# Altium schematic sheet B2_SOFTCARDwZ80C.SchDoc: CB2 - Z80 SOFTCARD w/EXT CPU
size A1; CheckedBy: SRKH; Engineer: SRKH; DocumentNumber: 1; Revision: 1.00; SheetNumber: 1; SheetTotal: 21; PageSetup: Record=PageOptions|CenterHorizontal=True|CenterVertical=True|PrintScale=0.50|XCorrection=1.00|YCorrection=1.00|PrintKind=2|BorderSize=5000000|LeftOffset=0|BottomOffset=0|Orientation=2|PaperLength=1000|PaperWidth=1000|Scale=100|PaperSource=7|PrintQuality=-4|MediaType=1|DitherType=10|PaperKind=A3 (297 x 420mm)|PrintScaleMode=1
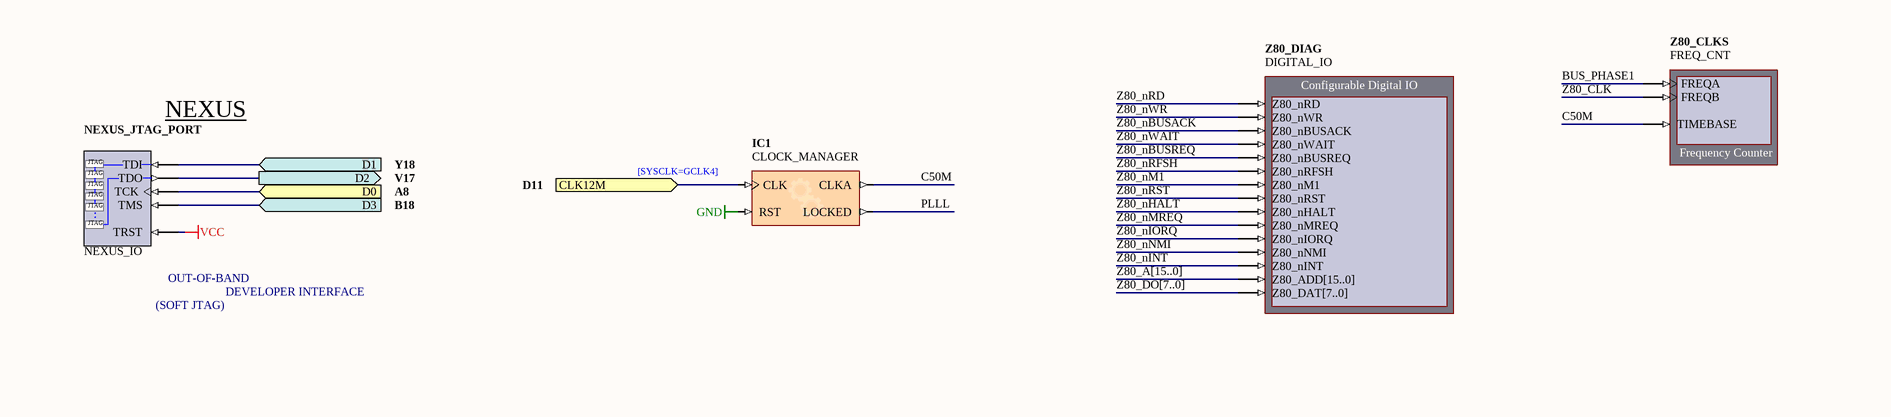
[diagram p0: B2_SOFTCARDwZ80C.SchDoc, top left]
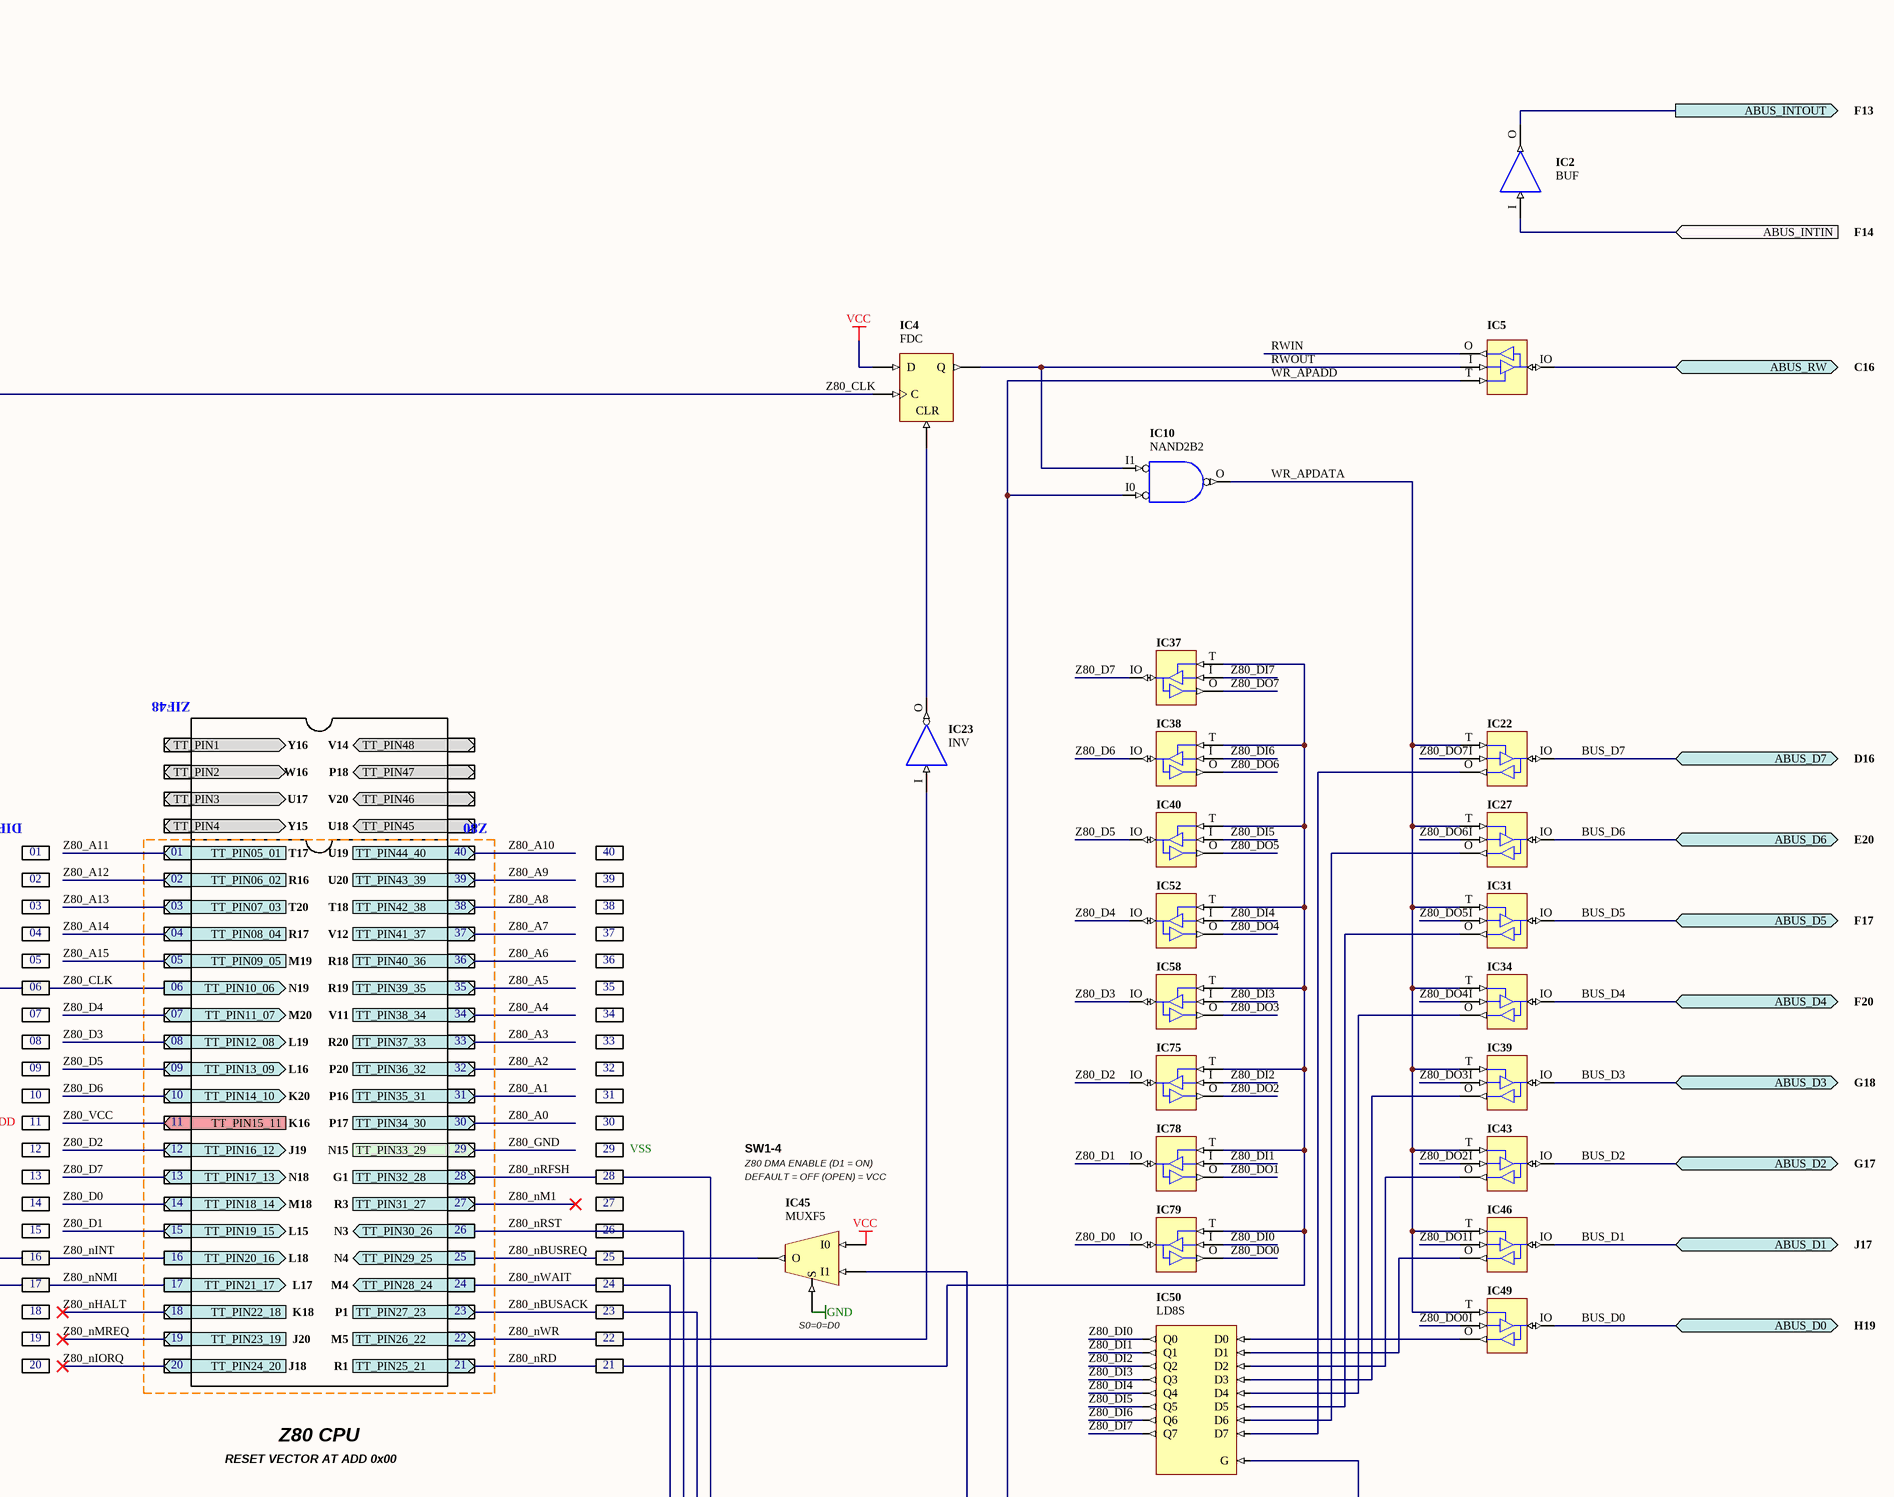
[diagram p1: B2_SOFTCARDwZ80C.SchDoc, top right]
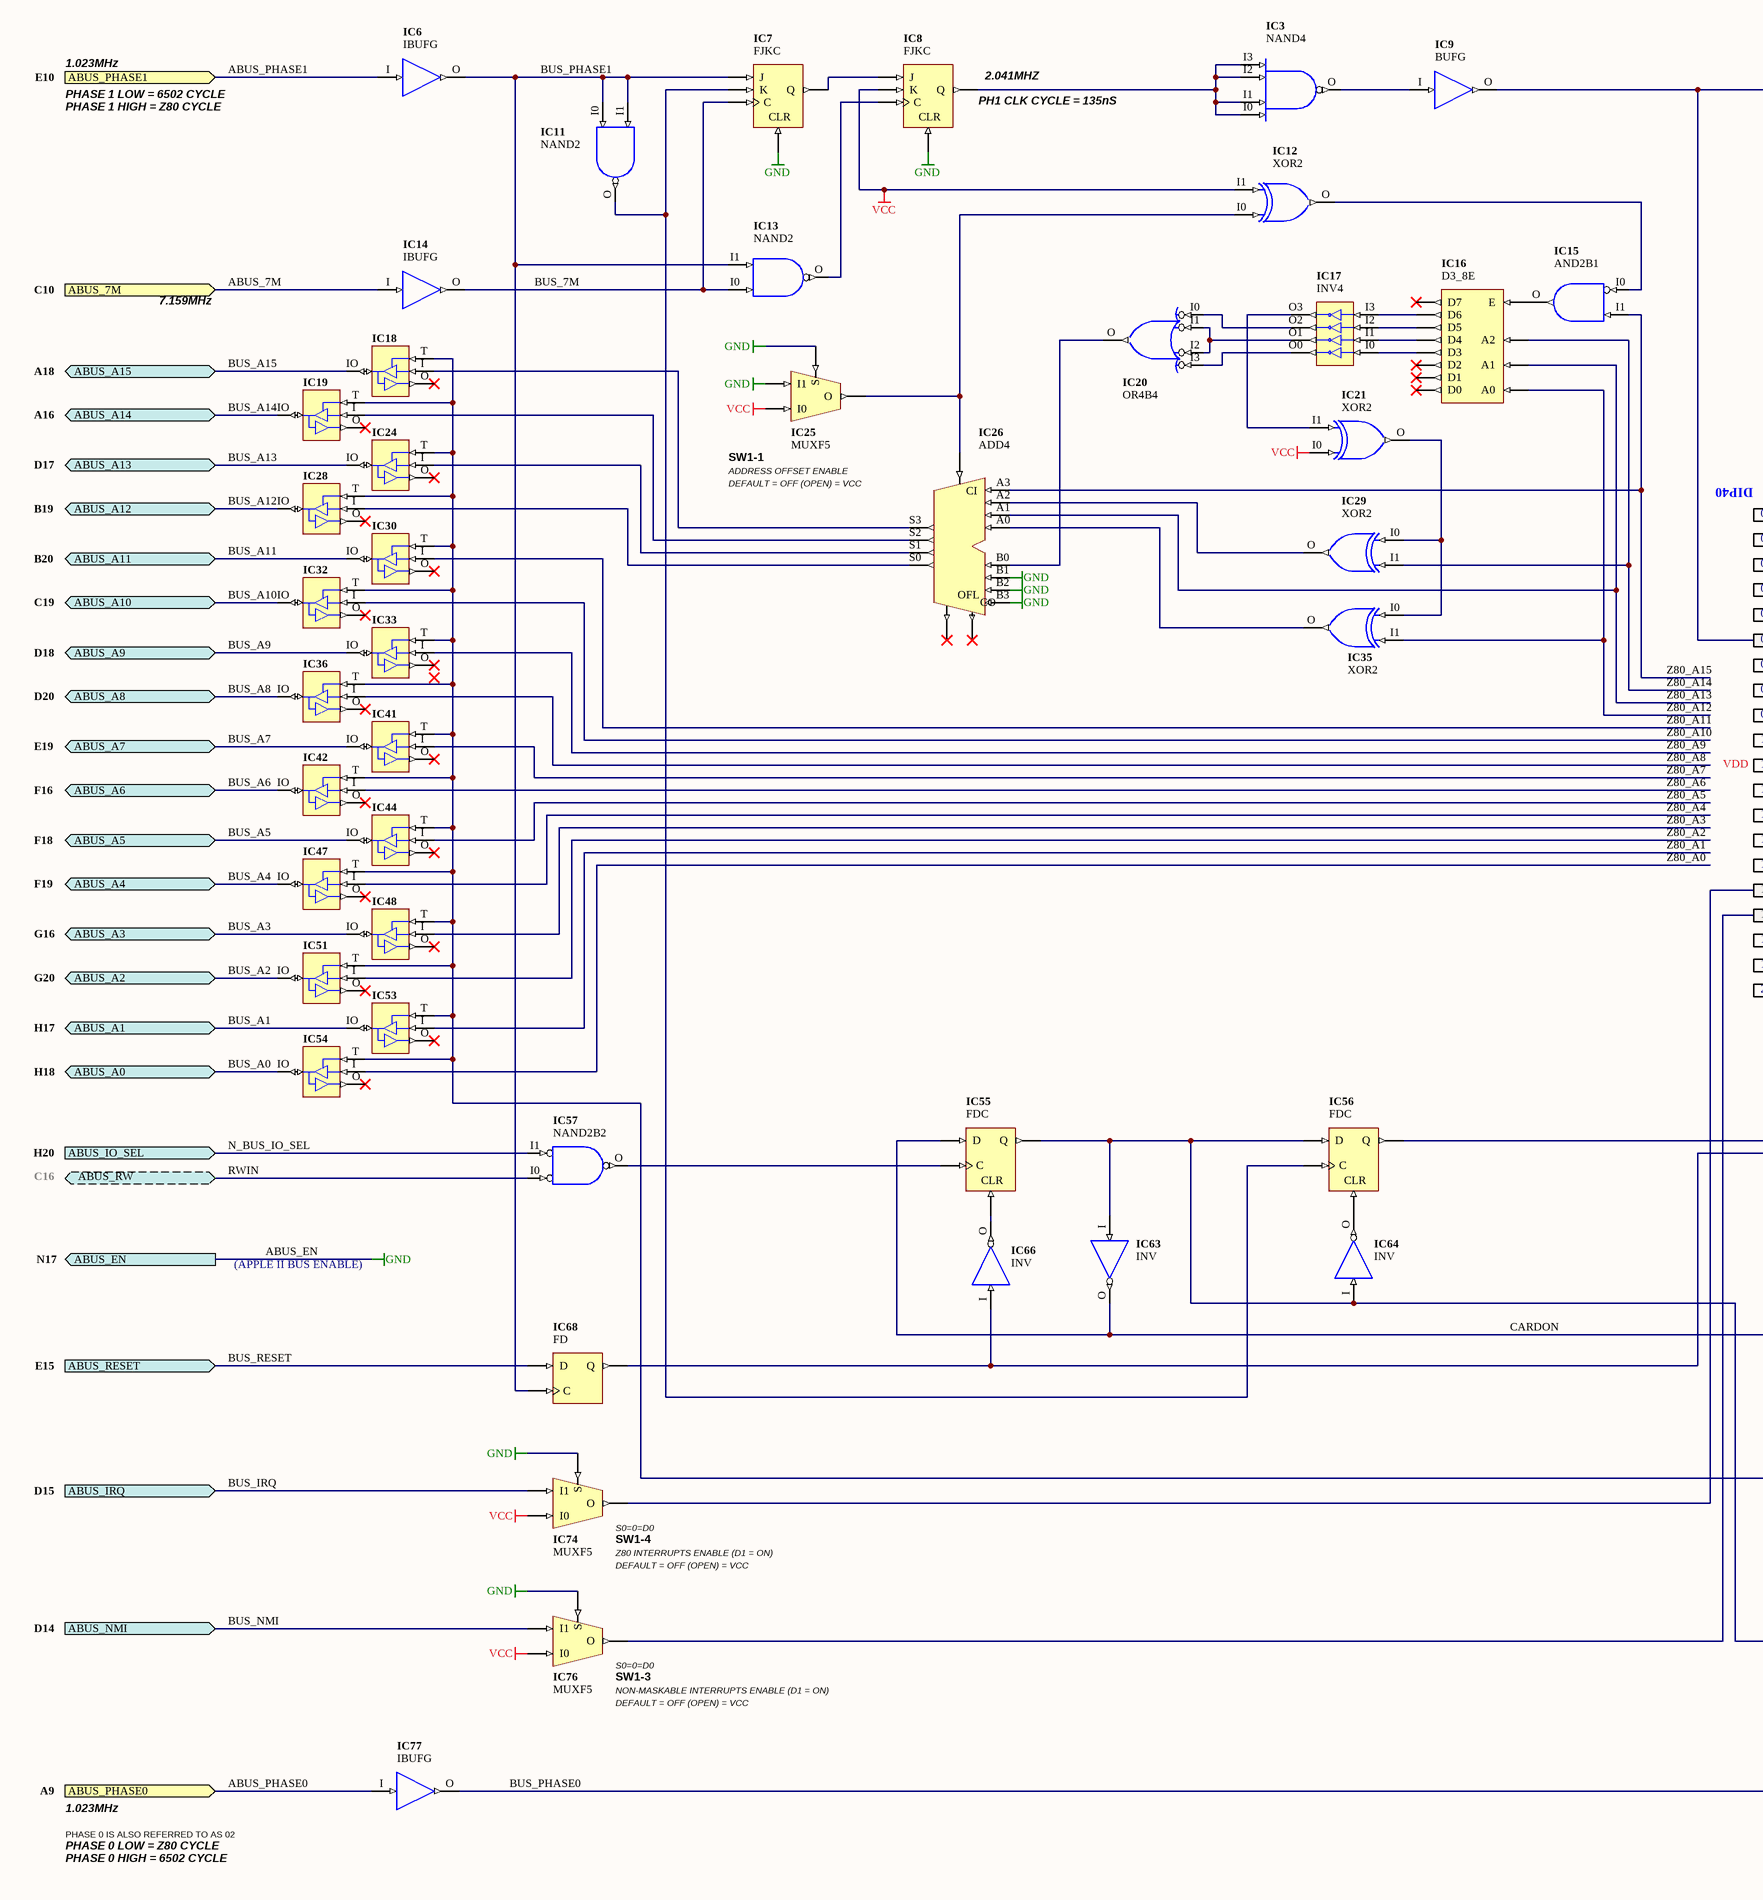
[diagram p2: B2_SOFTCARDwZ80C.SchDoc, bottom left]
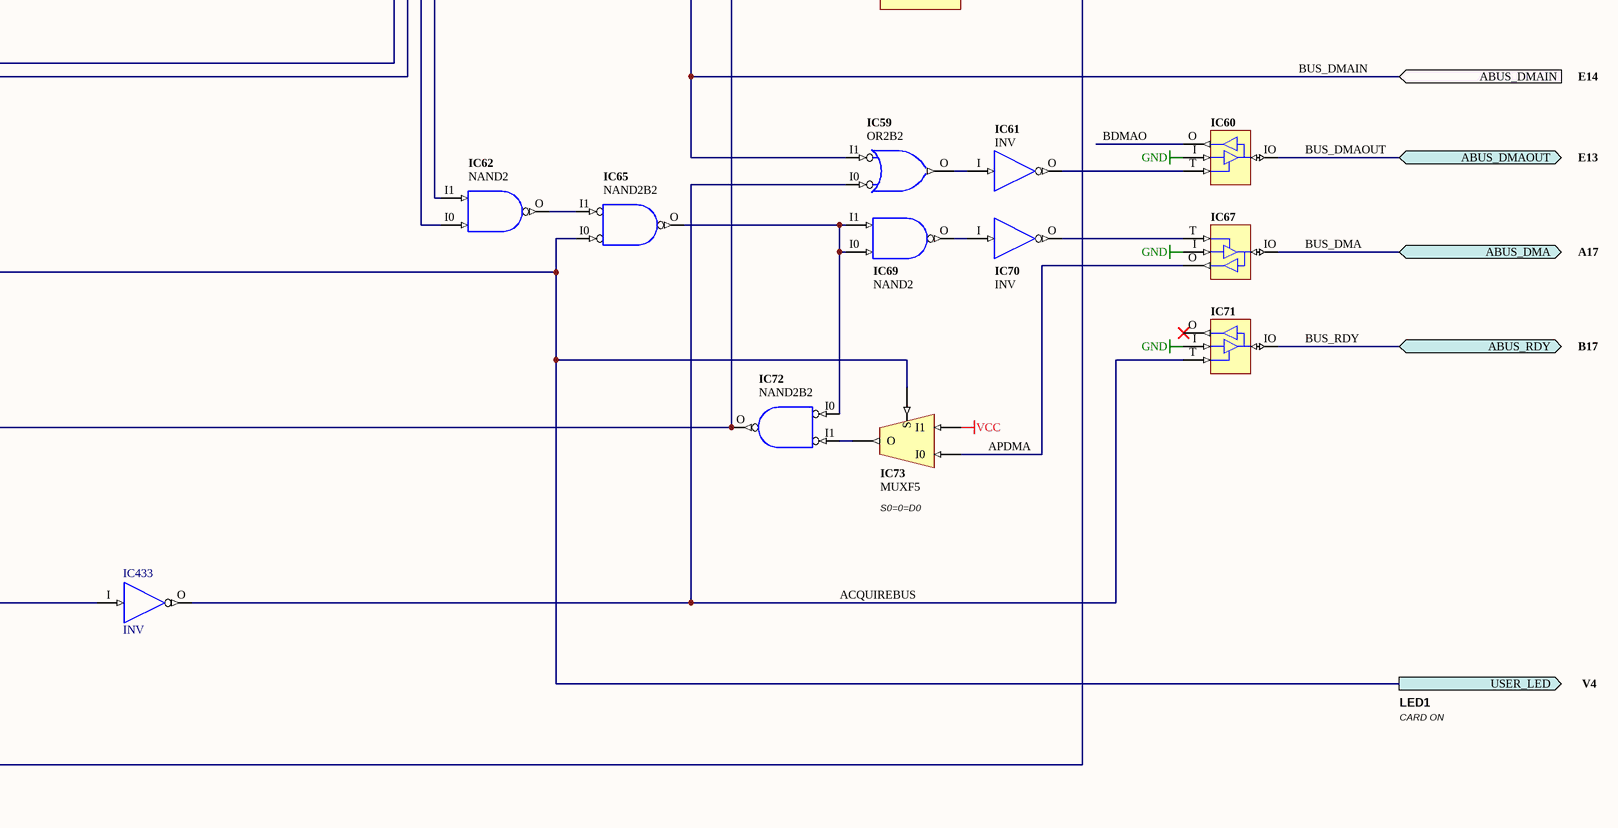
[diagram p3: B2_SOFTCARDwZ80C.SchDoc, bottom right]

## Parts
IC1  CLOCK_MANAGER
IC2  BUF
IC3  NAND4
IC4  FDC
IC5  IOBUF  (value not drawn)
IC6  IBUFG
IC7  FJKC
IC8  FJKC
IC9  BUFG
IC10  NAND2B2
IC11  NAND2
IC12  XOR2
IC13  NAND2
IC14  IBUFG
IC15  AND2B1
IC16  D3_8E
IC17  INV4
IC18  IOBUF  (value not drawn)
IC19  IOBUF  (value not drawn)
IC20  OR4B4
IC21  XOR2
IC22  IOBUF  (value not drawn)
IC23  INV
IC24  IOBUF  (value not drawn)
IC25  MUXF5
IC26  ADD4
IC27  IOBUF  (value not drawn)
IC28  IOBUF  (value not drawn)
IC29  XOR2
IC30  IOBUF  (value not drawn)
IC31  IOBUF  (value not drawn)
IC32  IOBUF  (value not drawn)
IC33  IOBUF  (value not drawn)
IC34  IOBUF  (value not drawn)
IC35  XOR2
IC36  IOBUF  (value not drawn)
IC37  IOBUF  (value not drawn)
IC38  IOBUF  (value not drawn)
IC39  IOBUF  (value not drawn)
IC40  IOBUF  (value not drawn)
IC41  IOBUF  (value not drawn)
IC42  IOBUF  (value not drawn)
IC43  IOBUF  (value not drawn)
IC44  IOBUF  (value not drawn)
IC45  MUXF5
IC46  IOBUF  (value not drawn)
IC47  IOBUF  (value not drawn)
IC48  IOBUF  (value not drawn)
IC49  IOBUF  (value not drawn)
IC50  LD8S
IC51  IOBUF  (value not drawn)
IC52  IOBUF  (value not drawn)
IC53  IOBUF  (value not drawn)
IC54  IOBUF  (value not drawn)
IC55  FDC
IC56  FDC
IC57  NAND2B2
IC58  IOBUF  (value not drawn)
IC59  OR2B2
IC60  IOBUF  (value not drawn)
IC61  INV
IC62  NAND2
IC63  INV
IC64  INV
IC65  NAND2B2
IC66  INV
IC67  IOBUF  (value not drawn)
IC68  FD
IC69  NAND2
IC70  INV
IC71  IOBUF  (value not drawn)
IC72  NAND2B2
IC73  MUXF5
IC74  MUXF5
IC75  IOBUF  (value not drawn)
IC76  MUXF5
IC77  IBUFG
IC78  IOBUF  (value not drawn)
IC79  IOBUF  (value not drawn)
IC433  INV
NEXUS_JTAG_PORT  NEXUS_IO
Z80_CLKS  FREQ_CNT
Z80_DIAG  DIGITAL_IO

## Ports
ABUS_7M (in, see C10), ABUS_A0 (bidir, see H18), ABUS_A1 (bidir, see H17), ABUS_A2 (bidir, see G20), ABUS_A3 (bidir, see G16), ABUS_A4 (bidir, see F19), ABUS_A5 (bidir, see F18), ABUS_A6 (bidir, see F16), ABUS_A7 (bidir, see E19), ABUS_A8 (bidir, see D20), ABUS_A9 (bidir, see D18), ABUS_A10 (bidir, see C19), ABUS_A11 (bidir, see B20), ABUS_A12 (bidir, see B19), ABUS_A13 (bidir, see D17), ABUS_A14 (bidir, see A16), ABUS_A15 (bidir, see A18), ABUS_D0 (bidir, see H19), ABUS_D1 (bidir, see J17), ABUS_D2 (bidir, see G17), ABUS_D3 (bidir, see G18), ABUS_D4 (bidir, see F20), ABUS_D5 (bidir, see F17), ABUS_D6 (bidir, see E20), ABUS_D7 (bidir, see D16), ABUS_DMA (bidir, see A17), ABUS_DMAIN (in, see E14), ABUS_DMAOUT (bidir, see E13), ABUS_EN (out, see N17), ABUS_INTIN (in, see F14), ABUS_INTOUT (out, see F13), ABUS_IO_SEL (in, see H20), ABUS_IRQ (in, see D15), ABUS_NMI (in, see D14), ABUS_PHASE0 (in, see A9), ABUS_PHASE1 (in, see E10), ABUS_RDY (bidir, see B17), ABUS_RESET (in, see E15), ABUS_RW (bidir, see C16), CLK12M (in, see D11), D0 (in, see A8), D1 (in, see Y18), D2 (out, see V17), D3 (in, see B18), TT_PIN1 (bidir, see Y16), TT_PIN2 (bidir, see W16), TT_PIN3 (bidir, see U17), TT_PIN4 (bidir, see Y15), TT_PIN05_01 (in, see T17), TT_PIN06_02 (in, see R16), TT_PIN07_03 (in, see T20), TT_PIN08_04 (in, see R17), TT_PIN09_05 (in, see M19), TT_PIN10_06 (out, see N19), TT_PIN11_07 (bidir, see M20), TT_PIN12_08 (bidir, see L19), TT_PIN13_09 (bidir, see L16), TT_PIN14_10 (bidir, see K20), TT_PIN15_11 (in, see K16), TT_PIN16_12 (bidir, see J19), TT_PIN17_13 (bidir, see N18), TT_PIN18_14 (bidir, see M18), TT_PIN19_15 (bidir, see L15), TT_PIN20_16 (out, see L18), TT_PIN21_17 (out, see L17), TT_PIN22_18 (in, see K18), TT_PIN23_19 (in, see J20), TT_PIN24_20 (in, see J18), TT_PIN25_21 (in, see R1), TT_PIN26_22 (in, see M5), TT_PIN27_23 (in, see P1), TT_PIN28_24 (out, see M4), TT_PIN29_25 (out, see N4), TT_PIN30_26 (out, see N3), TT_PIN31_27 (in, see R3), TT_PIN32_28 (in, see G1), TT_PIN33_29 (in, see N15), TT_PIN34_30 (in, see P17), TT_PIN35_31 (in, see P16), TT_PIN36_32 (in, see P20), TT_PIN37_33 (in, see R20), TT_PIN38_34 (in, see V11), TT_PIN39_35 (in, see R19), TT_PIN40_36 (in, see R18), TT_PIN41_37 (in, see V12), TT_PIN42_38 (in, see T18), TT_PIN43_39 (in, see U20), TT_PIN44_40 (in, see U19), TT_PIN45 (bidir, see U18), TT_PIN46 (bidir, see V20), TT_PIN47 (bidir, see P18), TT_PIN48 (bidir, see V14), USER_LED (out, see V4)

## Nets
ABUS_EN: IC1.RST IC7.CLR IC8.CLR IC25.I1 IC25.S IC26.B1 IC26.B2 IC26.B3 IC45.S IC60.I IC67.I IC71.I IC74.S IC76.S ; port ABUS_EN  [also labelled GND]
VCC: IC4.D IC8.K IC12.I1 IC21.I0 IC25.I0 IC45.I0 IC73.I1 IC74.I0 IC76.I0 NEXUS_JTAG_PORT.TRST
ABUS_7M: IC14.I ; port ABUS_7M
ABUS_INTIN: IC2.I ; port ABUS_INTIN
ABUS_INTOUT: IC2.O ; port ABUS_INTOUT
ABUS_PHASE0: IC77.I ; port ABUS_PHASE0
ABUS_PHASE1: IC6.I ; port ABUS_PHASE1
ABUS_RW: IC5.IO ; port ABUS_RW
ACQUIREBUS: IC59.I0 IC71.T IC433.O
APDMA: IC67.O IC73.I0
BDMAO: IC60.O
BUS_7M: IC7.C IC13.I0 IC14.O
BUS_A0: IC54.IO ; port ABUS_A0
BUS_A1: IC53.IO ; port ABUS_A1
BUS_A2: IC51.IO ; port ABUS_A2
BUS_A3: IC48.IO ; port ABUS_A3
BUS_A4: IC47.IO ; port ABUS_A4
BUS_A5: IC44.IO ; port ABUS_A5
BUS_A6: IC42.IO ; port ABUS_A6
BUS_A7: IC41.IO ; port ABUS_A7
BUS_A8: IC36.IO ; port ABUS_A8
BUS_A9: IC33.IO ; port ABUS_A9
BUS_A10: IC32.IO ; port ABUS_A10
BUS_A11: IC30.IO ; port ABUS_A11
BUS_A12: IC28.IO ; port ABUS_A12
BUS_A13: IC24.IO ; port ABUS_A13
BUS_A14: IC19.IO ; port ABUS_A14
BUS_A15: IC18.IO ; port ABUS_A15
BUS_D0: IC49.IO ; port ABUS_D0
BUS_D1: IC46.IO ; port ABUS_D1
BUS_D2: IC43.IO ; port ABUS_D2
BUS_D3: IC39.IO ; port ABUS_D3
BUS_D4: IC34.IO ; port ABUS_D4
BUS_D5: IC31.IO ; port ABUS_D5
BUS_D6: IC27.IO ; port ABUS_D6
BUS_D7: IC22.IO ; port ABUS_D7
BUS_DMA: IC67.IO ; port ABUS_DMA
BUS_DMAIN: IC45.I1 IC59.I1 ; port ABUS_DMAIN
BUS_DMAOUT: IC60.IO ; port ABUS_DMAOUT
BUS_IRQ: IC74.I1 ; port ABUS_IRQ
BUS_NMI: IC76.I1 ; port ABUS_NMI
BUS_PHASE0: IC50.G IC77.O
BUS_PHASE1: IC6.O IC7.J IC11.I0 IC11.I1 IC13.I1 IC68.C Z80_CLKS.FREQA
BUS_RDY: IC71.IO ; port ABUS_RDY
BUS_RESET: IC68.D ; port ABUS_RESET
C50M: IC1.CLKA Z80_CLKS.TIMEBASE
CARDON: IC55.D IC63.O IC65.I0 IC73.S ; port USER_LED
CLK12M: IC1.CLK ; port CLK12M
D0: NEXUS_JTAG_PORT.TCK ; port D0
D1: NEXUS_JTAG_PORT.TDI ; port D1
D2: NEXUS_JTAG_PORT.TDO ; port D2
D3: NEXUS_JTAG_PORT.TMS ; port D3
N_BUS_IO_SEL: IC57.I1 ; port ABUS_IO_SEL
PLLL: IC1.LOCKED
RWIN: IC5.O IC57.I0
RWOUT: IC4.Q IC5.I IC10.I1
WR_APADD: IC5.T IC10.I0 IC18.T IC19.T IC24.T IC28.T IC30.T IC32.T IC33.T IC36.T IC41.T IC42.T IC44.T IC47.T IC48.T IC51.T IC53.T IC54.T IC72.O
WR_APDATA: IC10.O IC22.T IC27.T IC31.T IC34.T IC39.T IC43.T IC46.T IC49.T
Z80_A0: IC54.I ; port TT_PIN34_30
Z80_A1: IC53.I ; port TT_PIN35_31
Z80_A2: IC51.I ; port TT_PIN36_32
Z80_A3: IC48.I ; port TT_PIN37_33
Z80_A4: IC47.I ; port TT_PIN38_34
Z80_A5: IC44.I ; port TT_PIN39_35
Z80_A6: IC42.I ; port TT_PIN40_36
Z80_A7: IC41.I ; port TT_PIN41_37
Z80_A8: IC36.I ; port TT_PIN42_38
Z80_A9: IC33.I ; port TT_PIN43_39
Z80_A10: IC32.I ; port TT_PIN44_40
Z80_A11: IC30.I ; port TT_PIN05_01
Z80_A12: IC16.A0 IC35.I1 ; port TT_PIN06_02
Z80_A13: IC16.A1 IC26.A1 ; port TT_PIN07_03
Z80_A14: IC16.A2 IC29.I1 ; port TT_PIN08_04
Z80_A15: IC15.I1 IC26.A3 ; port TT_PIN09_05
Z80_CLK: IC4.C IC9.O Z80_CLKS.FREQB ; port TT_PIN10_06
Z80_D0: IC79.IO ; port TT_PIN18_14
Z80_D1: IC78.IO ; port TT_PIN19_15
Z80_D2: IC75.IO ; port TT_PIN16_12
Z80_D3: IC58.IO ; port TT_PIN12_08
Z80_D4: IC52.IO ; port TT_PIN11_07
Z80_D5: IC40.IO ; port TT_PIN13_09
Z80_D6: IC38.IO ; port TT_PIN14_10
Z80_D7: IC37.IO ; port TT_PIN17_13
Z80_DI0: IC50.Q0 IC79.I
Z80_DI1: IC50.Q1 IC78.I
Z80_DI2: IC50.Q2 IC75.I
Z80_DI3: IC50.Q3 IC58.I
Z80_DI4: IC50.Q4 IC52.I
Z80_DI5: IC40.I IC50.Q5
Z80_DI6: IC38.I IC50.Q6
Z80_DI7: IC37.I IC50.Q7
Z80_DO0: IC49.I IC79.O
Z80_DO1: IC46.I IC78.O
Z80_DO2: IC43.I IC75.O
Z80_DO3: IC39.I IC58.O
Z80_DO4: IC34.I IC52.O
Z80_DO5: IC31.I IC40.O
Z80_DO6: IC27.I IC38.O
Z80_DO7: IC22.I IC37.O
Z80_nBUSACK: IC62.I0 Z80_DIAG.Z80_nBUSACK ; port TT_PIN27_23
Z80_nBUSREQ: IC45.O Z80_DIAG.Z80_nBUSREQ ; port TT_PIN29_25
Z80_nHALT: Z80_DIAG.Z80_nHALT ; port TT_PIN22_18
Z80_nINT: IC74.O Z80_DIAG.Z80_nINT ; port TT_PIN20_16
Z80_nIORQ: Z80_DIAG.Z80_nIORQ ; port TT_PIN24_20
Z80_nM1: Z80_DIAG.Z80_nM1 ; port TT_PIN31_27
Z80_nMREQ: Z80_DIAG.Z80_nMREQ ; port TT_PIN23_19
Z80_nNMI: IC76.O Z80_DIAG.Z80_nNMI ; port TT_PIN21_17
Z80_nRD: IC37.T IC38.T IC40.T IC52.T IC58.T IC75.T IC78.T IC79.T Z80_DIAG.Z80_nRD ; port TT_PIN25_21
Z80_nRFSH: IC62.I1 Z80_DIAG.Z80_nRFSH ; port TT_PIN32_28
Z80_nRST: IC66.I IC68.Q Z80_DIAG.Z80_nRST ; port TT_PIN30_26
Z80_nWAIT: IC56.Q Z80_DIAG.Z80_nWAIT ; port TT_PIN28_24
Z80_nWR: IC23.I Z80_DIAG.Z80_nWR ; port TT_PIN26_22
NetIC3_I0: IC3.I0 IC3.I1 IC3.I2 IC3.I3 IC8.Q
NetIC3_O: IC3.O IC9.I
NetIC4_CLR: IC4.CLR IC23.O
NetIC7_K: IC7.K IC11.O IC56.C
NetIC7_Q: IC7.Q IC8.J
NetIC8_C: IC8.C IC13.O
NetIC12_I0: IC12.I0 IC25.O IC26.CI
NetIC12_O: IC12.O IC15.I0
NetIC15_O: IC15.O IC16.E
NetIC16_D3: IC16.D3 IC17.I0
NetIC16_D4: IC16.D4 IC17.I1
NetIC16_D5: IC16.D5 IC17.I2
NetIC16_D6: IC16.D6 IC17.I3
NetIC17_O0: IC17.O0 IC20.I3
NetIC17_O1: IC17.O1 IC20.I1 IC20.I2
NetIC17_O2: IC17.O2 IC20.I0
NetIC17_O3: IC17.O3 IC21.I1
NetIC18_I: IC18.I IC26.S3
NetIC19_I: IC19.I IC26.S2
NetIC20_O: IC20.O IC26.B0
NetIC21_O: IC21.O IC29.I0 IC35.I0
NetIC22_O: IC22.O IC50.D7
NetIC24_I: IC24.I IC26.S1
NetIC26_A0: IC26.A0 IC35.O
NetIC26_A2: IC26.A2 IC29.O
NetIC26_S0: IC26.S0 IC28.I
NetIC27_O: IC27.O IC50.D6
NetIC31_O: IC31.O IC50.D5
NetIC34_O: IC34.O IC50.D4
NetIC39_O: IC39.O IC50.D3
NetIC43_O: IC43.O IC50.D2
NetIC46_O: IC46.O IC50.D1
NetIC49_O: IC49.O IC50.D0
NetIC55_C: IC55.C IC57.O
NetIC55_CLR: IC55.CLR IC66.O
NetIC55_Q: IC55.Q IC56.D IC63.I IC64.I IC433.I
NetIC56_CLR: IC56.CLR IC64.O
NetIC59_O: IC59.O IC61.I
NetIC60_T: IC60.T IC61.O
NetIC62_O: IC62.O IC65.I1
NetIC65_O: IC65.O IC69.I0 IC69.I1 IC72.I0
NetIC67_T: IC67.T IC70.O
NetIC69_O: IC69.O IC70.I
NetIC72_I1: IC72.I1 IC73.O

Not connected (* = marked no-connect by the designer): IC16 D0* D1* D2* D7*; IC18 O*; IC19 O*; IC24 O*; IC26 CO* OFL*; IC28 O*; IC30 O*; IC32 O*; IC33 O*; IC36 O*; IC41 O*; IC42 O*; IC44 O*; IC47 O*; IC48 O*; IC51 O*; IC53 O*; IC54 O*; IC71 O*; Z80_DIAG Z80_ADD[15..0] Z80_DAT[7..0]

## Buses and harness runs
bus Z80_A[15..0]
bus Z80_DO[7..0]

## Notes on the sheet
- (near NEXUS_JTAG_PORT) NEXUS
- [SYSCLK=GCLK4]
- (SOFT JTAG)
- (near NEXUS_JTAG_PORT) OUT-OF-BAND
- DEVELOPER INTERFACE
- 1.023MHz
- (near IC8) 2.041MHZ
- PHASE 1 LOW = 6502 CYCLE
- PHASE 1 HIGH = Z80 CYCLE
- (near IC8) PH1 CLK CYCLE = 135nS
- 7.159MHz
- ZIF48
- SW1-1
- ADDRESS OFFSET ENABLE
- DEFAULT = OFF (OPEN) = VCC
- DIP40
- 01
- 40
- Z80
- 02
- 03
- 39
- 38
- 04
- 05
- 06
- 37
- 36
- 35
- 07
- 08
- 34
- 33
- VDD
- 09
- 10
- 11
- 32
- 31
- 30
- 12
- 13
- 29
- 28
- VSS
- SW1-4
- Z80 DMA ENABLE (D1 = ON)
- 14
- 15
- 16
- 27
- 26
- 25
- 17
- 18
- 24
- 23
- (near IC45) S0=0=D0
- 19
- 20
- 22
- 21
- RESET VECTOR AT ADD 0x00
- Z80 CPU
- C16
- ABUS_RW
- (APPLE II BUS ENABLE)
- (near IC74) S0=0=D0
- (near IC74) SW1-4
- Z80 INTERRUPTS ENABLE (D1 = ON)
- (near IC73) S0=0=D0
- (near IC76) SW1-3
- (near IC76) NON-MASKABLE INTERRUPTS ENABLE (D1 = ON)
- (near IC76) S0=0=D0
- (near IC76) DEFAULT = OFF (OPEN) = VCC
- LED1
- CARD ON
- PHASE 0 IS ALSO REFERRED TO AS 02
- PHASE 0 LOW = Z80 CYCLE
- PHASE 0 HIGH = 6502 CYCLE

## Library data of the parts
IC1 = CLOCKMANAGER: Configurable Clock Manager; ConfiguratorName: GENERIC_CLOCKMANAGER; ConfigurationParameters: {}Version[1.0]{}Option_Configuration[object _1: TClockManagerPersist / VersionMajor [ 0 / VersionMinor [ 0 / InputFreq [ 24.000000000000000000 / InputName [ 'CLK' / OutputTargets [ < / item / Name [ 'CLKA' / OutFreqMin [ 198.000000000000000000 / OutFreqMax [ 202.000000000000000000 / OutPostDivider [ 1.000000000000000000 / end> / OutputDevices [ < / item / Name [ 'Spartan3AN' / Valid [ True / OutputActuals [ < / item / Name [ 'CLK0' / Multipler [ 1.000000000000000000 / Divider [ 1.000000000000000000 / OutFreq [ 24.000000000000000000 / OutputMap [ 1 / end / item / Name [ 'CLK90' / Multipler [ 1.000000000000000000 / Divider [ 1.000000000000000000 / OutPhase [ 90.000000000000000000 / OutFreq [ 24.000000000000000000 / OutputMap [ 2 / end / item / Name [ 'CLK180' / Multipler [ 1.000000000000000000 / Divider [ 1.000000000000000000 / OutPhase [ 180.000000000000000000 / OutFreq [ 24.000000000000000000 / OutputMap [ 3 / end / item / Name [ 'CLK270' / Multipler [ 1.000000000000000000 / Divider [ 1.000000000000000000 / OutPhase [ 270.000000000000000000 / OutFreq [ 24.000000000000000000 / OutputMap [ 4 / end / item / Name [ 'CLK2X' / Multipler [ 2.000000000000000000 / Divider [ 1.000000000000000000 / OutFreq [ 48.000000000000000000 / OutputMap [ 5 / end / item / Name [ 'CLKDV' / Multipler [ 1.000000000000000000 / Divider [ 16.000000000000000000 / OutFreq [ 1.500000000000000000 / OutputMap [ 6 / end / item / Name [ 'CLK2X180' / Multipler [ 1.000000000000000000 / Divider [ 1.000000000000000000 / OutPhase [ 180.000000000000000000 / OutFreq [ 48.000000000000000000 / OutputMap [ 7 / end / item / Name [ 'CLKFX' / Multipler [ 25.000000000000000000 / Divider [ 3.000000000000000000 / OutFreq [ 200.000000000000000000 / OutputMap [ 0 / end / item / Name [ 'CLKFX180' / Multipler [ 1.000000000000000000 / Divider [ 1.000000000000000000 / OutPhase [ 180.000000000000000000 / OutFreq [ 200.000000000000000000 / OutputMap [ 8 / end> / InternalActuals [ <> / CustomVars [ <> / end> / MinInputFreq [ 1.000000000000000000 / MaxInputFreq [ 280.000000000000000000 / MinOutputFreq [ 18.000000000000000000 / MaxOutputFreq [ 210.000000000000000000 / MaxOutputCount [ 9 / end]{}
IC2 = BUF: Global Clock Buffer; FPGAVendor: Xilinx
IC3 = NAND4: 4-Input NAND Gate; FPGAVendor: Xilinx
IC4 IC55 IC56 = FDC: D Flip-Flop with Asynchronous Clear; FPGAVendor: Xilinx
IC5 IC18 IC19 IC22 IC24 IC27 IC28 IC30-IC34 IC36-IC44 IC46-IC49 IC51-IC54 IC58 IC60 IC67 IC71 IC75 IC78 IC79 = IOBUF: Bi-Directional Buffer using the LVTTL standard; FPGAVendor: Xilinx
IC6 IC14 IC77 = IBUFG: Dedicated Input Buffer using the LVTTL standard; FPGAVendor: Xilinx
IC7 IC8 = FJKC: J-K Flip-Flop with Asynchronous Clear; FPGAVendor: Xilinx
IC9 = BUFG: Global Clock Buffer; FPGAVendor: Xilinx
IC10 IC57 IC65 IC72 = NAND2B2: 2-Input NAND Gate with Two Inverted Inputs; FPGAVendor: Xilinx
IC11 IC13 IC62 IC69 = NAND2: 2-Input NAND Gate; FPGAVendor: Xilinx
IC12 IC21 IC29 IC35 = XOR2: 2-Input XOR Gate; FPGAVendor: Xilinx
IC15 = AND2B1: 2-Input AND Gate with One Inverted Input; FPGAVendor: Xilinx
IC16 = D3_8E: 3- to 8-Line Decoder/Demultiplexer with Enable; FPGAVendor: Xilinx
IC17 = INV4: 4 x Inverters; FPGAVendor: Xilinx
IC20 = OR4B4: 4-Input OR Gate with Four Inverted Inputs; FPGAVendor: Xilinx
IC23 IC61 IC63 IC64 IC66 IC70 IC433 = INV: Inverter; FPGAVendor: Xilinx
IC25 IC45 IC73 IC74 IC76 = MUXF5: 2-to-1 Lookup Table Multiplexer with General Output; FPGAVendor: Xilinx
IC26 = ADD4: 4-Bit Cascadable Full Adders with Carry-In, Carry-Out and Overflow; FPGAVendor: Xilinx
IC50 = LD8S: 8-Bit Transparent Data Latch, Single Pin Version; PortSize: 8; ArchiveName: GENERIC; VHDLIB_SIM: GENERIC_LIB
IC59 = OR2B2: 2-Input OR Gate with Two Inverted Inputs; FPGAVendor: Xilinx
IC68 = FD: D Flip-Flop; FPGAVendor: Xilinx
NEXUS_JTAG_PORT = NEXUS_JTAG_PORT: Soft Nexus-Chain Connector; NEXUS_JTAG_CONNECTOR: True
Z80_CLKS = FRQCNT2: Frequency Counter; NEXUS_CORE: Instrument; NEXUS_JTAG_DEVICE: True; NEXUS_JTAG_ORDER: 0
Z80_DIAG = DIGITAL_IO: Configurable Digital IO; NEXUS_CORE: Instrument; NEXUS_JTAG_DEVICE: True; NEXUS_JTAG_ORDER: 0; ConfigurationParameters: {}Version[2.0]{}StorageType[3]{}InterfaceType[Parallel]{}SchCompWidth[140]{}Input0Name[Z80_nRD]{}Input0Width[1]{}Input0InitValue[0]{}Input0Kind[LEDs]{}Input0LEDStyle[Red]{}Input1Name[Z80_nWR]{}Input1Width[1]{}Input1InitValue[0]{}Input1Kind[LEDs]{}Input1LEDStyle[Red]{}Input2Name[Z80_nBUSACK]{}Input2Width[1]{}Input2InitValue[0]{}Input2Kind[LEDs]{}Input2LEDStyle[Red]{}Input3Name[Z80_nWAIT]{}Input3Width[1]{}Input3InitValue[0]{}Input3Kind[LEDs]{}Input3LEDStyle[Red]{}Input4Name[Z80_nBUSREQ]{}Input4Width[1]{}Input4InitValue[0]{}Input4Kind[LEDs]{}Input4LEDStyle[Red]{}Input5Name[Z80_nRFSH]{}Input5Width[1]{}Input5InitValue[0]{}Input5Kind[LEDs]{}Input5LEDStyle[Red]{}Input6Name[Z80_nM1]{}Input6Width[1]{}Input6InitValue[0]{}Input6Kind[LEDs]{}Input6LEDStyle[Red]{}Input7Name[Z80_nRST]{}Input7Width[1]{}Input7InitValue[0]{}Input7Kind[LEDs]{}Input7LEDStyle[Red]{}Input8Name[Z80_nHALT]{}Input8Width[1]{}Input8InitValue[0]{}Input8Kind[LEDs]{}Input8LEDStyle[Red]{}Input9Name[Z80_nMREQ]{}Input9Width[1]{}Input9InitValue[0]{}Input9Kind[LEDs]{}Input9LEDStyle[Red]{}Input10Name[Z80_nIORQ]{}Input10Width[1]{}Input10InitValue[0]{}Input10Kind[LEDs]{}Input10LEDStyle[Red]{}Input11Name[Z80_nNMI]{}Input11Width[1]{}Input11InitValue[0]{}Input11Kind[LEDs]{}Input11LEDStyle[Red]{}Input12Name[Z80_nINT]{}Input12Width[1]{}Input12InitValue[0]{}Input12Kind[LEDs]{}Input12LEDStyle[Red]{}Input13Name[Z80_ADD{1}15..0{2}]{}Input13Width[16]{}Input13InitValue[0]{}Input13Kind[Numeric]{}Input13NumRadix[Hexadecimal]{}Input14Name[Z80_DAT{1}7..0{2}]{}Input14Width[8]{}Input14InitValue[0]{}Input14Kind[Numeric]{}Input14NumRadix[Hexadecimal]{}NoOutputs[ ]{}Designator[Z80_DIAG]{}InternalID[1]{}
